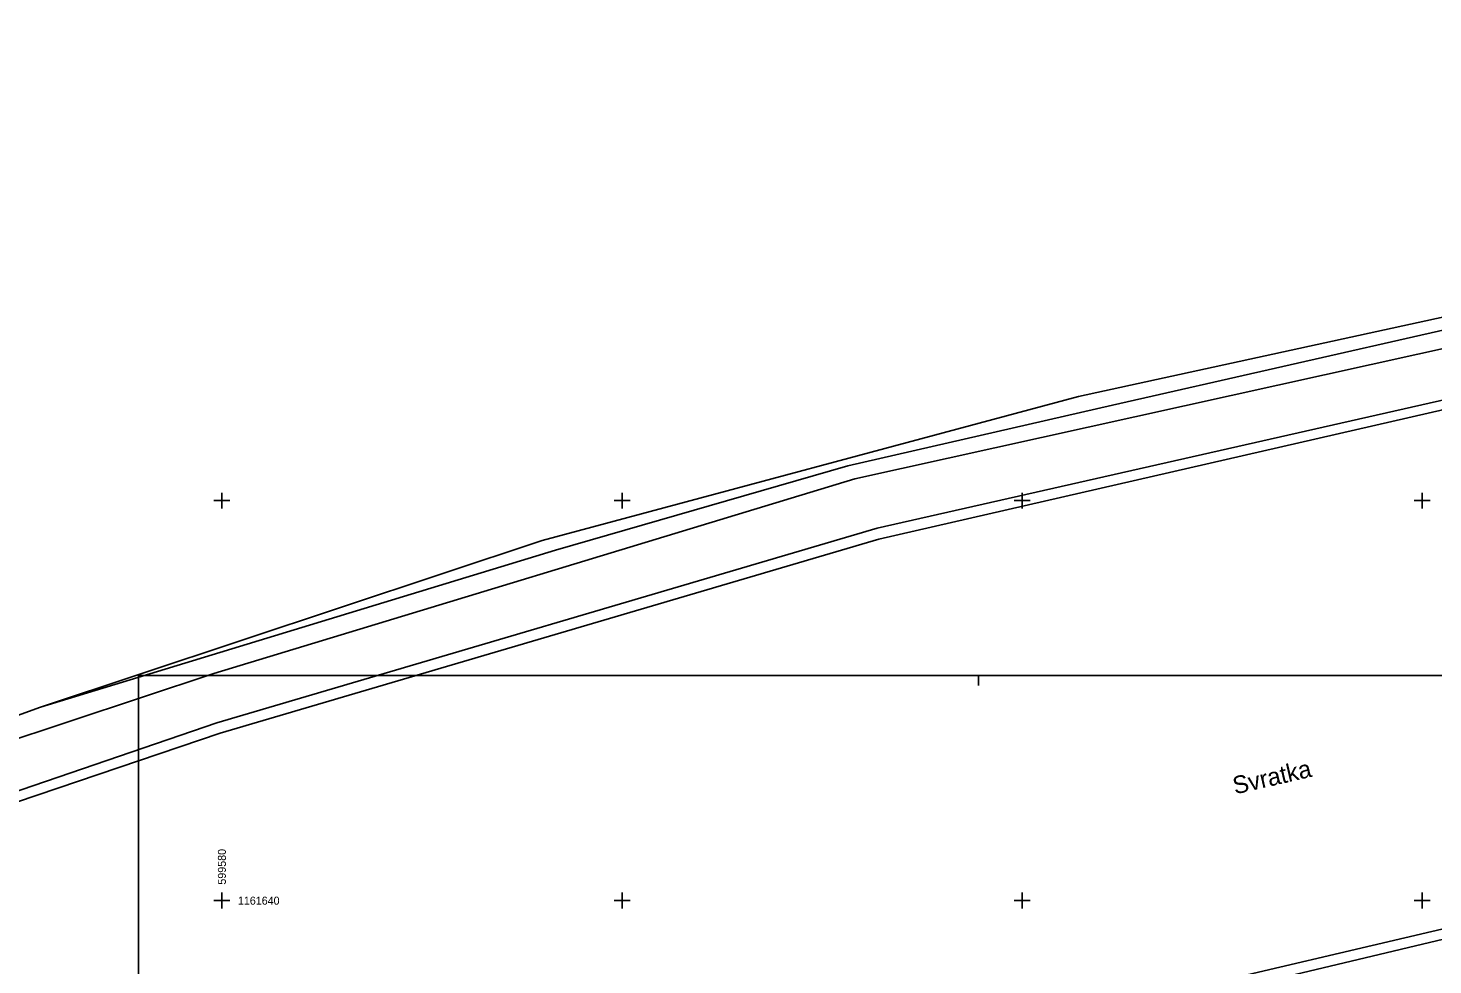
# Model space of a CAD drawing. Extents: x -599717 to -599336, y -1161826 to -1161587.
# Drawn here: x -599589.7 to -599519.5, y -1161643.2 to -1161596.4 of the extents above; entities that cross this region are included whole.
import ezdxf

# ---------------------------------------------------------------- set-up
doc = ezdxf.new("R2010")
doc.units = 0
for name, color, linetype in [('KN_Hranice parcel', 7, 'Continuous'), ('KN_Pop  PČ popisy', 7, 'Continuous'), ('KN_Vnitřní kresba', 7, 'Continuous'), ('X_RAM_ROZPISKA', 7, 'Continuous'), ('X_SOUR_KRIZKY_SEVER', 7, 'Continuous')]:
    doc.layers.add(name, color=color, linetype=linetype)

msp = doc.modelspace()

# ---------------------------------------------------------------- linework, layer by layer
at = {"layer": 'KN_Hranice parcel'}
for points in [[(-599436.5, -1161596.37), (-599461.75, -1161599.91), (-599505.29, -1161607.84), (-599537.18, -1161614.79), (-599564, -1161622), (-599589.06, -1161630.32)], [(-599589.06, -1161630.32), (-599606.5, -1161636.65), (-599615.27, -1161639.75)]]:
    msp.add_lwpolyline(points, dxfattribs=at)
at = {"layer": 'KN_Vnitřní kresba'}
for p, q in [((-599548.36, -1161618.9), (-599512.68, -1161611.01)), ((-599518.45, -1161611.35), (-599535.49, -1161615.22)), ((-599511.93, -1161613.38), (-599547.24, -1161621.37)), ((-599547.17, -1161621.93), (-599511.89, -1161613.83)), ((-599535.49, -1161615.22), (-599548.71, -1161618.25)), ((-599548.71, -1161618.25), (-599563.33, -1161622.47)), ((-599580.41, -1161628.64), (-599548.36, -1161618.9)), ((-599547.24, -1161621.37), (-599580.26, -1161631.11)), ((-599563.33, -1161622.47), (-599589.06, -1161630.32)), ((-599580.08, -1161631.62), (-599547.17, -1161621.93)), ((-599601.63, -1161635.68), (-599580.41, -1161628.64)), ((-599580.26, -1161631.11), (-599600.75, -1161638.14)), ((-599600.51, -1161638.56), (-599580.08, -1161631.62)), ((-599515.63, -1161640.62), (-599541.05, -1161646.59)), ((-599515.49, -1161641.11), (-599540.9, -1161647.14))]:
    msp.add_line(p, q, dxfattribs=at)
at = {"layer": 'X_RAM_ROZPISKA'}
for p, q in [((-599583.675, -1161628.735), (-599584.175, -1161628.735)), ((-599584.175, -1161628.735), (-599584.175, -1161629.235)), ((-599542.175, -1161628.735), (-599542.175, -1161629.235))]:
    msp.add_line(p, q, dxfattribs=at)
msp.add_lwpolyline([(-599584.175, -1161747.535), (-599458.175, -1161747.535), (-599458.175, -1161628.735), (-599584.175, -1161628.735)], close=True, dxfattribs=at)
at = {"layer": 'X_SOUR_KRIZKY_SEVER'}
for p, q in [((-599580, -1161620.4), (-599580, -1161619.6)), ((-599560, -1161620.4), (-599560, -1161619.6)), ((-599540, -1161620.4), (-599540, -1161619.6)), ((-599520, -1161620.4), (-599520, -1161619.6)), ((-599580.4, -1161620), (-599579.6, -1161620)), ((-599560.4, -1161620), (-599559.6, -1161620)), ((-599540.4, -1161620), (-599539.6, -1161620)), ((-599520.4, -1161620), (-599519.6, -1161620)), ((-599580.4, -1161640), (-599579.6, -1161640)), ((-599580, -1161640.4), (-599580, -1161639.6)), ((-599560.4, -1161640), (-599559.6, -1161640)), ((-599560, -1161640.4), (-599560, -1161639.6)), ((-599540.4, -1161640), (-599539.6, -1161640)), ((-599540, -1161640.4), (-599540, -1161639.6)), ((-599520.4, -1161640), (-599519.6, -1161640)), ((-599520, -1161640.4), (-599520, -1161639.6))]:
    msp.add_line(p, q, dxfattribs=at)

# ---------------------------------------------------------------- texts
at = {"layer": 'KN_Pop  PČ popisy'}
msp.add_text('Svratka', height=0.88, rotation=13, dxfattribs=at).set_placement((-599529.359, -1161634.693))
at = {"layer": 'X_SOUR_KRIZKY_SEVER'}
msp.add_text('599580', height=0.4, rotation=90, dxfattribs=at).set_placement((-599579.8, -1161639.2))
msp.add_text('1161640', height=0.4, dxfattribs=at).set_placement((-599579.2, -1161640.2))

doc.saveas('drawing.dxf')
